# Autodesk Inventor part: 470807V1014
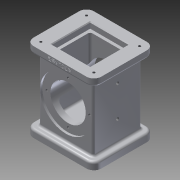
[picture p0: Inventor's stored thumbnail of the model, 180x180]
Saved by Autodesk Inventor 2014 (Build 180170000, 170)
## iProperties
Created: 2017-08
Part Number: 470807V1014
Material: 알루미늄 6061
Document SubType Name: Modeling
Designer: 학생용
Mass: 872.328 g
Surface Area: 642.25 cm^2
Volume: 321.892 cm^3
Density: 2.71 g/cm^3
Appearance: 알루미늄 - 평지
Author: 학생용
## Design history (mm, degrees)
sketch "스케치1"
  geometry: L1 (-36, -41)-(36, -41); L2 (46, -31)-(46, 31); L3 (36, 41)-(-36, 41); L4 (-46, 31)-(-46, -31); L5 (-46, -41)-(46, 41); L6 (46, -41)-(-46, 41); A1 r 10 centre (-36, 31) between (-36, 41) and (-46, 31); A2 r 10 centre (36, 31) between (46, 31) and (36, 41); A3 r 10 centre (36, -31) between (36, -41) and (46, -31); A4 r 10 centre (-36, -31) between (-46, -31) and (-36, -41); 1 further point
  constraints: 12 end point, 8 point on circle, 8 point on line, 8 tangent, 4 centre point, 3 equal radius, 2 midpoint, 2 parallel, 1 horizontal, 1 perpendicular
  dimensions: "d0" = 92 distance of L6.end L5.end; "d1" = 82 distance of L5.end L6.start; "d2" = 10 radius of A1
extrude "돌출1" new body sketch "스케치1" distance "d3" = 10; taper "d4" = 0 deg
node "작업 평면1"
sketch "스케치2"
  geometry: L1 (-36, -41)-(36, -41); L2 (46, -31)-(46, 31); L3 (36, 41)-(-36, 41); L4 (-46, 31)-(-46, -31); L5 (-46, -41)-(46, 41); L6 (46, -41)-(-46, 41); A1 r 10 centre (-36, 31) between (-36, 41) and (-46, 31); A2 r 10 centre (-36, -31) between (-46, -31) and (-36, -41); A3 r 10 centre (36, -31) between (36, -41) and (46, -31); A4 r 10 centre (36, 31) between (46, 31) and (36, 41); 1 further point
  constraints: 12 end point, 8 point on circle, 8 point on line, 8 tangent, 4 centre point, 3 equal radius, 2 midpoint, 2 parallel, 1 horizontal, 1 perpendicular
  dimensions: "d6" = 92 distance of L6.end L5.end; "d7" = 82 distance of L5.end L6.start; "d8" = 10 radius of A1
extrude "돌출2" join sketch "스케치2" distance "d9" = 10; taper "d10" = 0 deg
sketch "스케치3"
  geometry: L1 (-34, -33)-(34, -33); L2 (37, -30)-(37, 30); L3 (34, 33)-(-34, 33); L4 (-37, 30)-(-37, -30); L5 (-37, -33)-(37, 33); L6 (37, -33)-(-37, 33); A1 r 3 centre (-34, 30) between (-34, 33) and (-37, 30); A2 r 3 centre (-34, -30) between (-37, -30) and (-34, -33); A3 r 3 centre (34, -30) between (34, -33) and (37, -30); A4 r 3 centre (34, 30) between (37, 30) and (34, 33); 1 further point
  constraints: 12 end point, 8 point on circle, 8 point on line, 8 tangent, 4 centre point, 3 equal radius, 2 midpoint, 2 parallel, 1 horizontal, 1 perpendicular
  dimensions: "d11" = 74 distance of L6.end L5.end; "d12" = 66 distance of L5.end L6.start; "d31" = 3 radius of A1
extrude "돌출3" join sketch "스케치3" stored distance "d13" = 10; taper "d14" = 0 deg
sketch "스케치4"
  geometry: A1 r 10 centre (36, 31) between (46, 31) and (36, 41) reference; A2 r 10 centre (-36, 31) between (-36, 41) and (-46, 31) reference; A3 r 10 centre (-36, -31) between (-46, -31) and (-36, -41) reference; A4 r 10 centre (36, -31) between (36, -41) and (46, -31) reference; 5 further points
  constraints: 4 coincident
  dimensions: "d15" = 72 distance of point (36, 31) point (-36, 31) (derived); "d16" = 62 distance of point (36, -31) point (36, 31) (derived)
hole "구멍1" sketch "스케치4" at (-36, 31), (36, 31), (36, -31), (-36, -31) diameter "d17" = 3.242; stored, may be unused: countersink angle "d21" = 90 deg, drill point angle "d23" = 118 deg; dims "d18" = 4, "d19" = 4, "d20" = 2, "d22" = 6
sketch "스케치5"
  geometry: A1 r 10 centre (-36, -31) between (-46, -31) and (-36, -41) reference; A2 r 10 centre (36, -31) between (36, -41) and (46, -31) reference; A3 r 10 centre (36, 31) between (46, 31) and (36, 41) reference; A4 r 10 centre (-36, 31) between (-36, 41) and (-46, 31) reference; 5 further points
  constraints: 4 coincident
hole "구멍2" sketch "스케치5" at (36, 31), (36, -31), (-36, -31), (-36, 31) diameter "d24" = 3.242; stored, may be unused: countersink angle "d28" = 90 deg, drill point angle "d30" = 118 deg; dims "d25" = 4, "d26" = 4, "d27" = 2, "d29" = 6
sketch "스케치6"
  geometry: L1 (-21, -24)-(21, -24); L2 (24, -21)-(24, 21); L3 (21, 24)-(-21, 24); L4 (-24, 21)-(-24, -21); L5 (-24, -24)-(24, 24); L6 (24, -24)-(-24, 24); A1 r 3 centre (-21, 21) between (-21, 24) and (-24, 21); A2 r 3 centre (21, -21) between (21, -24) and (24, -21); A3 r 3 centre (21, 21) between (24, 21) and (21, 24); A4 r 3 centre (-21, 21) between (-21, 24) and (-24, 21); A5 r 3 centre (-21, -21) between (-24, -21) and (-21, -24); 3 further points
  constraints: 12 end point, 10 point on circle, 10 point on line, 10 tangent, 5 centre point, 4 equal radius, 3 midpoint, 2 parallel, 2 perpendicular, 1 coincident, 1 horizontal
  dimensions: "d32" = 48 distance of L5.end L6.end; "d33" = 3 radius of A1
extrude "돌출4" cut sketch "스케치6" distance "d34" = 16; taper "d35" = 0 deg
fillet "모깎기2" dims "d37" = 3
sketch "스케치7"
  geometry: L1 (-26, -26)-(26, -26); L2 (26, -26)-(26, 26); L3 (26, 26)-(-26, 26); L4 (-26, 26)-(-26, -26); L5 (-26, -26)-(26, 26); L6 (26, -26)-(-26, 26); 1 further point
  constraints: 12 end point, 2 midpoint, 2 parallel, 2 perpendicular, 1 horizontal
  dimensions: "d38" = 52 distance of L2.end L3.end
extrude "돌출5" cut sketch "스케치7" distance "d39" = 8; taper "d40" = 0 deg
sketch "스케치8"
  geometry: L1 (-19, -22)-(19, -22); L2 (22, -19)-(22, 19); L3 (19, 22)-(-19, 22); L4 (-22, 19)-(-22, -19); L5 (-22, -22)-(22, 22); L6 (22, -22)-(-22, 22); A1 r 3 centre (-19, 19) between (-19, 22) and (-22, 19); A2 r 3 centre (-19, -19) between (-22, -19) and (-19, -22); A3 r 3 centre (19, -19) between (19, -22) and (22, -19); A4 r 3 centre (19, 19) between (22, 19) and (19, 22); 3 further points
  constraints: 12 end point, 8 point on circle, 8 point on line, 8 tangent, 4 centre point, 3 equal radius, 3 midpoint, 2 parallel, 2 perpendicular, 1 coincident, 1 horizontal
  dimensions: "d41" = 44 distance of L5.end L6.end; "d42" = 3 radius of A1
extrude "돌출6" cut sketch "스케치8" distance "d43" = 74; taper "d44" = 0 deg
chamfer "모따기1" distance "d45" = 1; stored, may be unused: second distance "d46" = 2, angle "d47" = 45 deg
sketch "스케치9"
  geometry: L1 (54, 41)-(54, -41); L2 (13, 33)-(95, 33) reference; L3 (98, 36)-(98, 38) reference; L4 (101, 41)-(108, 41) reference; L5 (108, 41)-(108, 27) reference; L6 (108, 27)-(107, 26) reference; L7 (107, 26)-(100, 26) reference; L8 (100, 26)-(100, 22) reference; L9 (100, 22)-(26, 22) reference; L10 (26, 22)-(26, -22) reference; L11 (26, -22)-(100, -22) reference; L12 (100, -22)-(100, -26) reference; L13 (100, -26)-(107, -26) reference; L14 (107, -26)-(108, -27) reference; L15 (108, -27)-(108, -41) reference; L16 (108, -41)-(101, -41) reference; L17 (98, -38)-(98, -36) reference; L18 (95, -33)-(13, -33) reference; L19 (10, -36)-(10, -38) reference; L20 (7, -41)-(0, -41) reference; L21 (0, -41)-(0, -24) reference; L22 (0, -24)-(13, -24) reference; L23 (16, -21)-(16, 21) reference; L24 (13, 24)-(0, 24) reference; L25 (0, 24)-(0, 41) reference; L26 (0, 41)-(7, 41) reference; L27 (10, 38)-(10, 36) reference; L28 (89, -30)-(78, -30); L29 (78, -30)-(78, -22); L30 (78, -22)-(54, -22); L31 (89, -30)-(89, -33); L32 (89, -33)-(54, -33); L33 (54, 22)-(78, 22); L34 (78, 22)-(78, 30); L35 (78, 30)-(89, 30); L36 (89, 30)-(89, 33); L37 (89, 33)-(54, 33); L38 (54, -33)-(54, -22); L39 (54, 22)-(54, 33); L40 (78, -22)-(78, 22); A1 r 3 centre (13, 36) between (10, 36) and (13, 33) reference; A2 r 3 centre (95, 36) between (95, 33) and (98, 36) reference; A3 r 3 centre (101, 38) between (101, 41) and (98, 38) reference; A4 r 3 centre (101, -38) between (98, -38) and (101, -41) reference; A5 r 3 centre (95, -36) between (98, -36) and (95, -33) reference; A6 r 3 centre (13, -36) between (13, -33) and (10, -36) reference; A7 r 3 centre (7, -38) between (7, -41) and (10, -38) reference; A8 r 3 centre (13, -21) between (13, -24) and (16, -21) reference; A9 r 3 centre (13, 21) between (16, 21) and (13, 24) reference; A10 r 3 centre (7, 38) between (10, 38) and (7, 41) reference; 1 further point
  constraints: 28 end point, 7 point on line, 3 perpendicular, 2 horizontal alignment, 2 parallel, 1 collinear, 1 horizontal, 1 midpoint, 1 vertical
  dimensions: "d48" = 54 distance from line of point (0, 0) L1; "d50" = 3 distance of L28.start L31.end; "d51" = 70 diameter of L31 L1; "d52" = 48 diameter of L29 L1; "d53" = 8 distance of L28.end L29.end; "d54" = 3 distance of L35.end L36.end; "d55" = 8 distance of L33.end L34.end; "d56" = 48 diameter of L34 L1; "d57" = 70 diameter of L36 L1
revolve "회전1" sketch "스케치9" stored, may be unused: angle "d58" = 90 deg
sketch "스케치10"
  geometry: C1 r 35 at (0, 0) reference; C2 r 24 at (0, 0) reference; A1 r 29 centre (0, 0) between (0, 29) and (-29, 0); 3 further points
  constraints: 4 point on circle, 2 horizontal alignment, 2 vertical alignment, 1 centre point, 1 coincident
  dimensions: "d59" = 58 diameter of A1
hole "구멍3" sketch "스케치10" at (0, 29), (-29, 0), (0, -29), (29, 0) diameter "d60" = 3.242; stored, may be unused: countersink angle "d64" = 90 deg, drill point angle "d66" = 118 deg; dims "d61" = 4, "d62" = 4, "d63" = 2, "d65" = 6
sketch "스케치11"
  geometry: C1 r 24 at (0, 0) reference; C2 r 35 at (0, 0) reference; A1 r 29 centre (0, 0) between (0, 29) and (-29, 0); 3 further points
  constraints: 4 point on circle, 2 horizontal alignment, 2 vertical alignment, 1 centre point, 1 coincident
  dimensions: "d67" = 58 diameter of A1
hole "구멍4" sketch "스케치11" at (0, 29), (-29, 0), (0, -29), (29, 0) diameter "d68" = 3.242; stored, may be unused: countersink angle "d72" = 90 deg, drill point angle "d74" = 118 deg; dims "d69" = 4, "d70" = 4, "d71" = 2, "d73" = 6
sketch "스케치12"
  geometry: L1 (0, 82)-(60, 82) reference; L2 (-1, -13)-(61, -13) reference; 4 further points
  constraints: 2 vertical alignment, 1 midpoint
  dimensions: "d75" = 38 distance from line of L2 point (30, 25); "d76" = 42 distance of point (30, 67) point (30, 25)
sketch "스케치13"
  geometry: L1 (72, 0)-(0, 0) reference; L2 (-10, 0)-(-10, -7) reference; 2 further points
  constraints: 1 other
  dimensions: "d84" = 4 distance from line of L1 point (36, -4); "d85" = 46 distance from line of L2 point (36, -4)
feature "엠보싱1" sketch "스케치13" dims "d0" = 92, "d1" = 82, "d2" = 10, "d86" = 0.5, "d87" = 0
hole "구멍6" sketch "스케치12" diameter "d88" = 4.134; stored, may be unused: countersink angle "d92" = 90 deg, drill point angle "d94" = 118 deg; dims "d89" = 6, "d90" = 4, "d91" = 2, "d93" = 20
fillet "모깎기3" dims "d95" = 3
node "솔리드1"
node "절단 모서리 투영1"
other parameters: "d5" = -108
